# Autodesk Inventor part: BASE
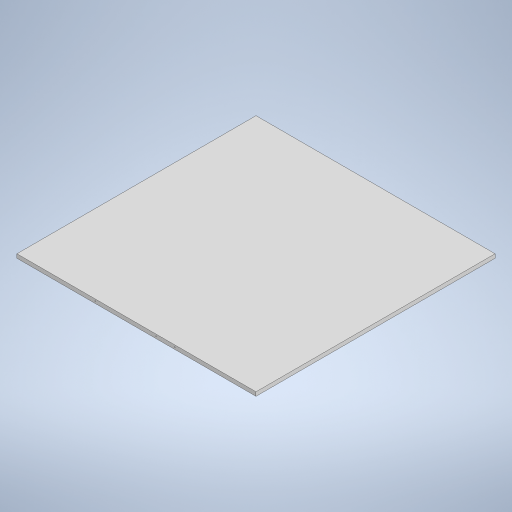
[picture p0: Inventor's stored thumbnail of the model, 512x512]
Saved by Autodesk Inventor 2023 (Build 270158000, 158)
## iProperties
Created: 2022-06
Part Number: BASE
Material: Generic
Document SubType Name: Modeling
Designer: prana_p9lsmih
Density: 1 g/cm^3
Appearance: Default
Author: prana_p9lsmih
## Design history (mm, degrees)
sketch "Sketch1"
  geometry: L1 (0, 0)-(610, 0); L2 (610, 0)-(610, -610); L3 (610, -610)-(0, -610); L4 (0, -610)-(0, 0)
  constraints: 8 end point, 2 parallel, 1 horizontal, 1 perpendicular
  dimensions: "d0" = 610 distance of L2.end L3.end; "d1" = 610 distance of L1.end L2.end
extrude "Extrusion1" new body sketch "Sketch1" distance "d2" = 10; taper "d3" = 0 deg
sketch "Sketch2"
  geometry: L1 (0, 0)-(610, 0) reference; L2 (0, 0)-(0, 10) reference; 1 further point
  dimensions: "d4" = 5 distance from line of L1 point (200, 5); "d5" = 200 distance from line of L2 point (200, 5)
hole "Hole1" sketch "Sketch2" at (200, 5) diameter "d6" = 2; stored, may be unused: countersink angle "d10" = 90 deg, drill point angle "d12" = 118 deg; dims "d7" = 6, "d8" = 4, "d9" = 2, "d11" = 10
pattern_linear "Rectangular Pattern2" dims "d27" = 155
sketch "Sketch4"
  geometry: L1 (0, 0)-(610, 0) reference; L2 (610, 0)-(610, 10) reference; 1 further point
  dimensions: "d28" = 5 distance from line of L1 point (402.5, 5); "d29" = 207.5 distance from line of L2 point (402.5, 5)
hole "Hole3" sketch "Sketch4" at (402.5, 5) diameter "d30" = 2; stored, may be unused: countersink angle "d34" = 90 deg, drill point angle "d36" = 118 deg; dims "d31" = 6, "d32" = 4, "d33" = 2, "d35" = 10
body "Solid1"
